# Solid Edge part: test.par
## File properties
Title: Thrust bearing
Author: Abhinav Rai
Template: Normal.par
Last saved by: CADCIM
Revision: 12
Application: Solid Edge
Accuracy: 0.99
Material: aluminum
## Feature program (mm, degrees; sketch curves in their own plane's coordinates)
sketch for "unnamed RevolvedProtrusion 1" plane through (0, 0, 0) normal (0, -1, 0) x-axis (1, 0, 0)
  line (47.625, 16.8036) -> (66.929, 16.8036)
  line (66.929, 16.8036) -> (73.025, 10.7076)
  line (73.025, 10.7076) -> (73.025, -12.0254)
  line (73.025, -12.0254) -> (66.929, -18.1214)
  line (66.929, -18.1214) -> (47.625, -18.1214)
  line (47.625, -18.1214) -> (47.625, -7.1994)
  line (61.5714, -7.1994) -> (47.625, -7.1994)
  line (61.5714, 5.8816) -> (61.5714, -7.1994)
  line (47.625, 5.8816) -> (61.5714, 5.8816)
  line (47.625, 5.8816) -> (47.625, 16.8036)
revolve "unnamed RevolvedProtrusion 1" add finite 360 deg
sketch for "unnamed RevolvedProtrusion 2" plane through (0, 0, 0) normal (1, 0, 0) x-axis (0, 1, 0)
  line (69.977, 13.7556) -> (73.0652, 13.7556)
  line (73.0652, 13.7556) -> (74.6125, 12.2083)
  line (74.6125, 12.2083) -> (74.6125, -13.4669)
  line (74.6125, -13.4669) -> (73.006, -15.0734)
  line (73.006, -15.0734) -> (69.977, -15.0734)
revolve "unnamed RevolvedProtrusion 2" add full turn 360 deg
sketch for "unnamed RevolvedProtrusion 3" plane through (0, 0, 0) normal (0, -1, 0) x-axis (1, 0, 0)
revolve "unnamed RevolvedProtrusion 3" add full turn 360 deg about sketch line (-54.9674, 10.1232) -> (-54.9674, -18.1214)
pattern "unnamed Pattern 1" of "unnamed RevolvedProtrusion 3"
pattern "unnamed Pattern 2"
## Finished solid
Body 1: solid body, 39 faces, 39 edges, 25 vertices.
  Faces by surface: torus 25, plane 6, cone 4, cylinder 4
  Edges by curve: circle 39
Bounding box of the edges (mm; curved faces can reach further): 149.225 x 149.225 x 34.925, from (-74.6125, -74.6125, -18.1214) to (74.6125, 74.6125, 16.8036).
Cylindrical faces by radius (mm): R47.625 x2, R61.5714 x1, R74.6125 x1
Conical faces (half-angle, radius in mm at the cone's reference point): 45 deg R66.929 x1, 45 deg R73.025 x1, 45 deg R73.0652 x1, 45 deg R74.6125 x1
Toroidal faces (ring radius, tube radius in mm): R-0.1023 r6.604 x25
Planar faces by outward normal: +z 3, -z 3
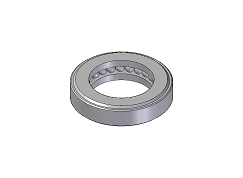
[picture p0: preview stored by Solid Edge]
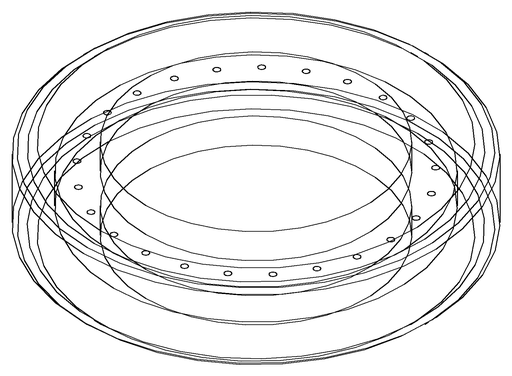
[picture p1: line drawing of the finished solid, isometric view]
